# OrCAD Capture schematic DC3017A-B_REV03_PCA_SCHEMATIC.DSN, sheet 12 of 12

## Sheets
12 _10-PORTS 1-12 LEDS: size Custom
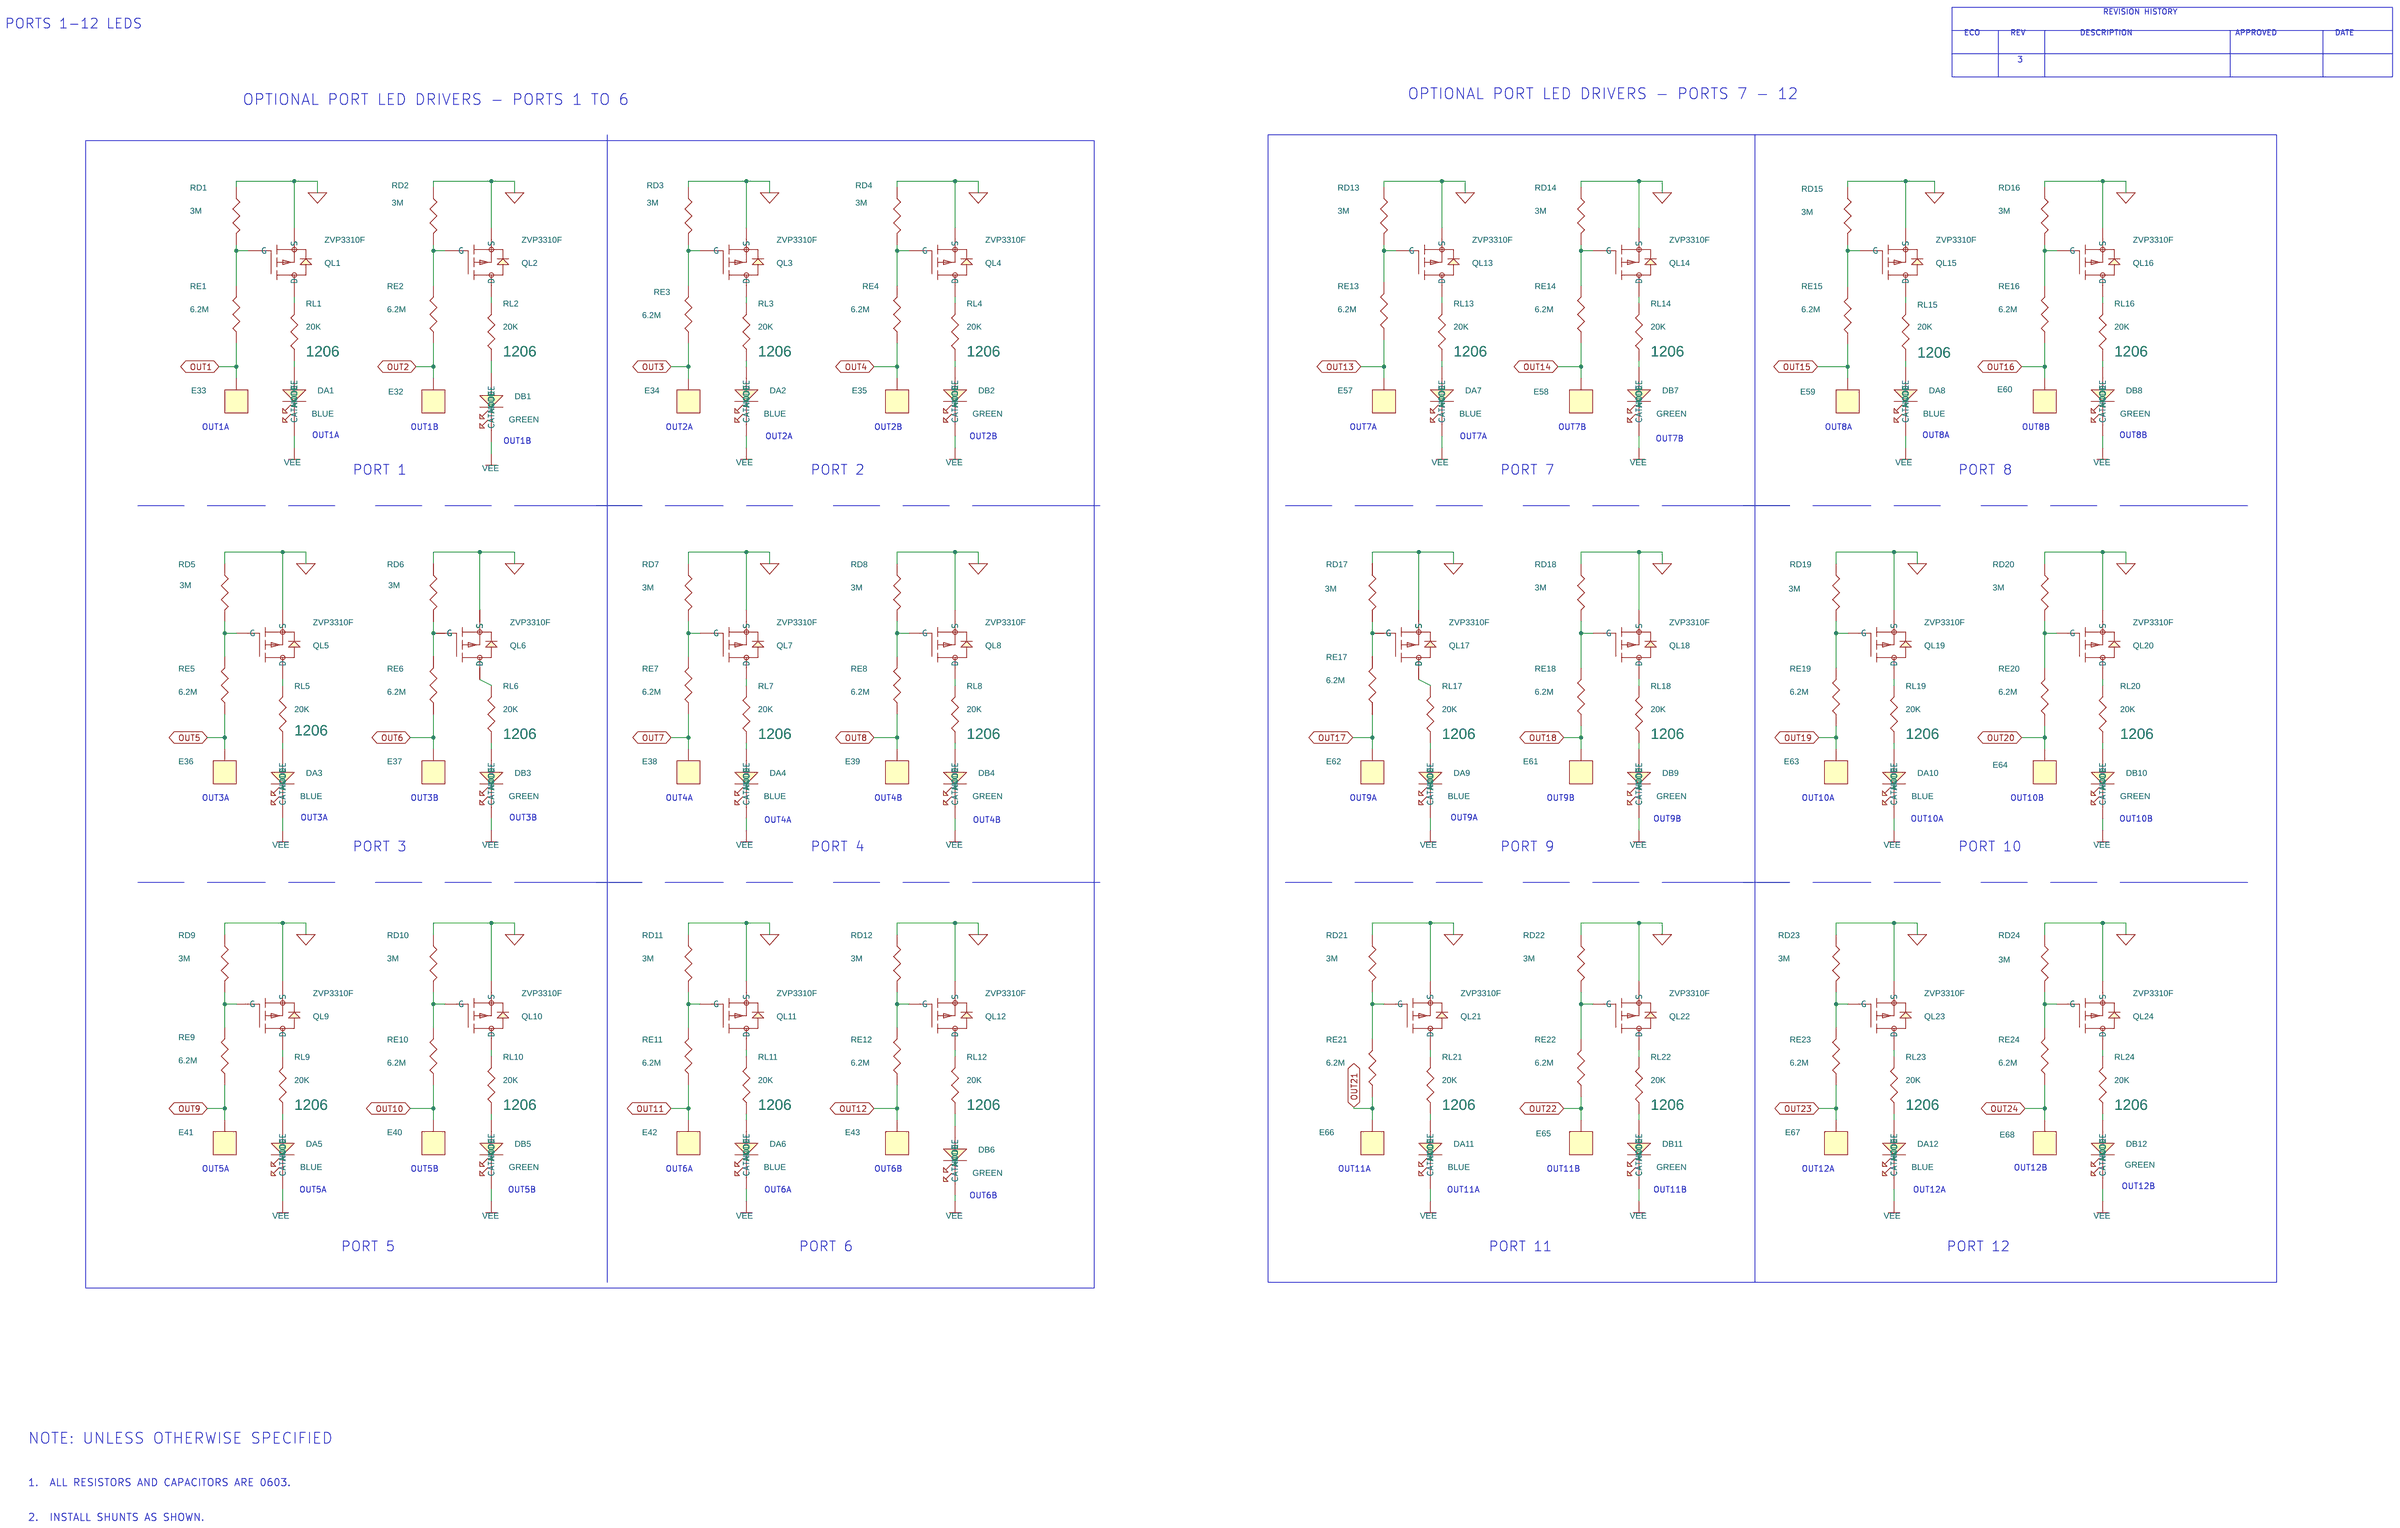
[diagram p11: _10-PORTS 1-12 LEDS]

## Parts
DA1  BLUE  [LED_0603]
DA2  BLUE  [LED_0603]
DA3  BLUE  [LED_0603]
DA4  BLUE  [LED_0603]
DA5  BLUE  [LED_0603]
DA6  BLUE  [LED_0603]
DA7  BLUE  [LED_0603]
DA8  BLUE  [LED_0603]
DA9  BLUE  [LED_0603]
DA10  BLUE  [LED_0603]
DA11  BLUE  [LED_0603]
DA12  BLUE  [LED_0603]
DB1  GREEN  [LED_0603]
DB2  GREEN  [LED_0603]
DB3  GREEN  [LED_0603]
DB4  GREEN  [LED_0603]
DB5  GREEN  [LED_0603]
DB6  GREEN  [LED_0603]
DB7  GREEN  [LED_0603]
DB8  GREEN  [LED_0603]
DB9  GREEN  [LED_0603]
DB10  GREEN  [LED_0603]
DB11  GREEN  [LED_0603]
DB12  GREEN  [LED_0603]
E32  TEST POINT  [KEYSTONE_5019]
E33  TEST POINT  [KEYSTONE_5019]
E34  TEST POINT  [KEYSTONE_5019]
E35  TEST POINT  [KEYSTONE_5019]
E36  TEST POINT  [KEYSTONE_5019]
E37  TEST POINT  [KEYSTONE_5019]
E38  TEST POINT  [KEYSTONE_5019]
E39  TEST POINT  [KEYSTONE_5019]
E40  TEST POINT  [KEYSTONE_5019]
E41  TEST POINT  [KEYSTONE_5019]
E42  TEST POINT  [KEYSTONE_5019]
E43  TEST POINT  [KEYSTONE_5019]
E57  TEST POINT  [KEYSTONE_5019]
E58  TEST POINT  [KEYSTONE_5019]
E59  TEST POINT  [KEYSTONE_5019]
E60  TEST POINT  [KEYSTONE_5019]
E61  TEST POINT  [KEYSTONE_5019]
E62  TEST POINT  [KEYSTONE_5019]
E63  TEST POINT  [KEYSTONE_5019]
E64  TEST POINT  [KEYSTONE_5019]
E65  TEST POINT  [KEYSTONE_5019]
E66  TEST POINT  [KEYSTONE_5019]
E67  TEST POINT  [KEYSTONE_5019]
E68  TEST POINT  [KEYSTONE_5019]
QL1  ZVP3310F  [SOT23-3N]
QL2  ZVP3310F  [SOT23-3N]
QL3  ZVP3310F  [SOT23-3N]
QL4  ZVP3310F  [SOT23-3N]
QL5  ZVP3310F  [SOT23-3N]
QL6  ZVP3310F  [SOT23-3N]
QL7  ZVP3310F  [SOT23-3N]
QL8  ZVP3310F  [SOT23-3N]
QL9  ZVP3310F  [SOT23-3N]
QL10  ZVP3310F  [SOT23-3N]
QL11  ZVP3310F  [SOT23-3N]
QL12  ZVP3310F  [SOT23-3N]
QL13  ZVP3310F  [SOT23-3N]
QL14  ZVP3310F  [SOT23-3N]
QL15  ZVP3310F  [SOT23-3N]
QL16  ZVP3310F  [SOT23-3N]
QL17  ZVP3310F  [SOT23-3N]
QL18  ZVP3310F  [SOT23-3N]
QL19  ZVP3310F  [SOT23-3N]
QL20  ZVP3310F  [SOT23-3N]
QL21  ZVP3310F  [SOT23-3N]
QL22  ZVP3310F  [SOT23-3N]
QL23  ZVP3310F  [SOT23-3N]
QL24  ZVP3310F  [SOT23-3N]
RD1  3M  [CR0603N]
RD2  3M  [CR0603N]
RD3  3M  [CR0603N]
RD4  3M  [CR0603N]
RD5  3M  [CR0603N]
RD6  3M  [CR0603N]
RD7  3M  [CR0603N]
RD8  3M  [CR0603N]
RD9  3M  [CR0603N]
RD10  3M  [CR0603N]
RD11  3M  [CR0603N]
RD12  3M  [CR0603N]
RD13  3M  [CR0603N]
RD14  3M  [CR0603N]
RD15  3M  [CR0603N]
RD16  3M  [CR0603N]
RD17  3M  [CR0603N]
RD18  3M  [CR0603N]
RD19  3M  [CR0603N]
RD20  3M  [CR0603N]
RD21  3M  [CR0603N]
RD22  3M  [CR0603N]
RD23  3M  [CR0603N]
RD24  3M  [CR0603N]
RE1  6.2M  [CR0603N]
RE2  6.2M  [CR0603N]
RE3  6.2M  [CR0603N]
RE4  6.2M  [CR0603N]
RE5  6.2M  [CR0603N]
RE6  6.2M  [CR0603N]
RE7  6.2M  [CR0603N]
RE8  6.2M  [CR0603N]
RE9  6.2M  [CR0603N]
RE10  6.2M  [CR0603N]
RE11  6.2M  [CR0603N]
RE12  6.2M  [CR0603N]
RE13  6.2M  [CR0603N]
RE14  6.2M  [CR0603N]
RE15  6.2M  [CR0603N]
RE16  6.2M  [CR0603N]
RE17  6.2M  [CR0603N]
RE18  6.2M  [CR0603N]
RE19  6.2M  [CR0603N]
RE20  6.2M  [CR0603N]
RE21  6.2M  [CR0603N]
RE22  6.2M  [CR0603N]
RE23  6.2M  [CR0603N]
RE24  6.2M  [CR0603N]
RL1  20K  [CR1206N]
RL2  20K  [CR1206N]
RL3  20K  [CR1206N]
RL4  20K  [CR1206N]
RL5  20K  [CR1206N]
RL6  20K  [CR1206N]
RL7  20K  [CR1206N]
RL8  20K  [CR1206N]
RL9  20K  [CR1206N]
RL10  20K  [CR1206N]
RL11  20K  [CR1206N]
RL12  20K  [CR1206N]
RL13  20K  [CR1206N]
RL14  20K  [CR1206N]
RL15  20K  [CR1206N]
RL16  20K  [CR1206N]
RL17  20K  [CR1206N]
RL18  20K  [CR1206N]
RL19  20K  [CR1206N]
RL20  20K  [CR1206N]
RL21  20K  [CR1206N]
RL22  20K  [CR1206N]
RL23  20K  [CR1206N]
RL24  20K  [CR1206N]

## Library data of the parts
DA1 = LED: LED,BLUE,WATER CLEAR,0603; 1ST PART FIELD: OUT1A; CLASS: DISCRETE; Inventory Qty: 0; Manufacturer: Wurth Elektronik; Manufacturer PN: 155060BS75300; PART_NUMBER: 270-0164; Package Type: 0603
DA2 = LED: LED,BLUE,WATER CLEAR,0603; 1ST PART FIELD: OUT3A; CLASS: DISCRETE; Inventory Qty: 0; Manufacturer: Wurth Elektronik; Manufacturer PN: 155060BS75300; PART_NUMBER: 270-0164; Package Type: 0603
DA3 = LED: LED,BLUE,WATER CLEAR,0603; 1ST PART FIELD: OUT2A; CLASS: DISCRETE; Inventory Qty: 0; Manufacturer: Wurth Elektronik; Manufacturer PN: 155060BS75300; PART_NUMBER: 270-0164; Package Type: 0603
DA4 = LED: LED,BLUE,WATER CLEAR,0603; 1ST PART FIELD: OUT4A; CLASS: DISCRETE; Inventory Qty: 0; Manufacturer: Wurth Elektronik; Manufacturer PN: 155060BS75300; PART_NUMBER: 270-0164; Package Type: 0603
DA5 = LED: LED,BLUE,WATER CLEAR,0603; 1ST PART FIELD: OUT5A; CLASS: DISCRETE; Inventory Qty: 0; Manufacturer: Wurth Elektronik; Manufacturer PN: 155060BS75300; PART_NUMBER: 270-0164; Package Type: 0603
DA6 = LED: LED,BLUE,WATER CLEAR,0603; 1ST PART FIELD: OUT6A; CLASS: DISCRETE; Inventory Qty: 0; Manufacturer: Wurth Elektronik; Manufacturer PN: 155060BS75300; PART_NUMBER: 270-0164; Package Type: 0603
DA7 = LED: LED,BLUE,WATER CLEAR,0603; 1ST PART FIELD: OUT7A; CLASS: DISCRETE; Inventory Qty: 0; Manufacturer: Wurth Elektronik; Manufacturer PN: 155060BS75300; PART_NUMBER: 270-0164; Package Type: 0603
DA8 = LED: LED,BLUE,WATER CLEAR,0603; 1ST PART FIELD: OUT8A; CLASS: DISCRETE; Inventory Qty: 0; Manufacturer: Wurth Elektronik; Manufacturer PN: 155060BS75300; PART_NUMBER: 270-0164; Package Type: 0603
DA9 = LED: LED,BLUE,WATER CLEAR,0603; 1ST PART FIELD: OUT9A; CLASS: DISCRETE; Inventory Qty: 0; Manufacturer: Wurth Elektronik; Manufacturer PN: 155060BS75300; PART_NUMBER: 270-0164; Package Type: 0603
DA10 = LED: LED,BLUE,WATER CLEAR,0603; 1ST PART FIELD: OUT10A; CLASS: DISCRETE; Inventory Qty: 0; Manufacturer: Wurth Elektronik; Manufacturer PN: 155060BS75300; PART_NUMBER: 270-0164; Package Type: 0603
DA11 = LED: LED,BLUE,WATER CLEAR,0603; 1ST PART FIELD: OUT11A; CLASS: DISCRETE; Inventory Qty: 0; Manufacturer: Wurth Elektronik; Manufacturer PN: 155060BS75300; PART_NUMBER: 270-0164; Package Type: 0603
DA12 = LED: LED,BLUE,WATER CLEAR,0603; 1ST PART FIELD: OUT12A; CLASS: DISCRETE; Inventory Qty: 0; Manufacturer: Wurth Elektronik; Manufacturer PN: 155060BS75300; PART_NUMBER: 270-0164; Package Type: 0603
DB1 = LED: LED,GREEN,DIFFUSED,0603; 1ST PART FIELD: OUT1B; CLASS: DISCRETE; Inventory Qty: 4424; Manufacturer: ROHM; Manufacturer PN: SML-E12P8WT86; PART_NUMBER: 270-0176; Package Type: 0603
DB2 = LED: LED,GREEN,DIFFUSED,0603; 1ST PART FIELD: OUT3B; CLASS: DISCRETE; Inventory Qty: 4424; Manufacturer: ROHM; Manufacturer PN: SML-E12P8WT86; PART_NUMBER: 270-0176; Package Type: 0603
DB3 = LED: LED,GREEN,DIFFUSED,0603; 1ST PART FIELD: OUT2B; CLASS: DISCRETE; Inventory Qty: 4424; Manufacturer: ROHM; Manufacturer PN: SML-E12P8WT86; PART_NUMBER: 270-0176; Package Type: 0603
DB4 = LED: LED,GREEN,DIFFUSED,0603; 1ST PART FIELD: OUT4B; CLASS: DISCRETE; Inventory Qty: 4424; Manufacturer: ROHM; Manufacturer PN: SML-E12P8WT86; PART_NUMBER: 270-0176; Package Type: 0603
DB5 = LED: LED,GREEN,DIFFUSED,0603; 1ST PART FIELD: OUT5B; CLASS: DISCRETE; Inventory Qty: 4424; Manufacturer: ROHM; Manufacturer PN: SML-E12P8WT86; PART_NUMBER: 270-0176; Package Type: 0603
DB6 = LED: LED,GREEN,DIFFUSED,0603; 1ST PART FIELD: OUT6B; CLASS: DISCRETE; Inventory Qty: 4424; Manufacturer: ROHM; Manufacturer PN: SML-E12P8WT86; PART_NUMBER: 270-0176; Package Type: 0603
DB7 = LED: LED,GREEN,DIFFUSED,0603; 1ST PART FIELD: OUT7B; CLASS: DISCRETE; Inventory Qty: 4424; Manufacturer: ROHM; Manufacturer PN: SML-E12P8WT86; PART_NUMBER: 270-0176; Package Type: 0603
DB8 = LED: LED,GREEN,DIFFUSED,0603; 1ST PART FIELD: OUT8B; CLASS: DISCRETE; Inventory Qty: 4424; Manufacturer: ROHM; Manufacturer PN: SML-E12P8WT86; PART_NUMBER: 270-0176; Package Type: 0603
DB9 = LED: LED,GREEN,DIFFUSED,0603; 1ST PART FIELD: OUT9B; CLASS: DISCRETE; Inventory Qty: 4424; Manufacturer: ROHM; Manufacturer PN: SML-E12P8WT86; PART_NUMBER: 270-0176; Package Type: 0603
DB10 = LED: LED,GREEN,DIFFUSED,0603; 1ST PART FIELD: OUT10B; CLASS: DISCRETE; Inventory Qty: 4424; Manufacturer: ROHM; Manufacturer PN: SML-E12P8WT86; PART_NUMBER: 270-0176; Package Type: 0603
DB11 = LED: LED,GREEN,DIFFUSED,0603; 1ST PART FIELD: OUT11B; CLASS: DISCRETE; Inventory Qty: 4424; Manufacturer: ROHM; Manufacturer PN: SML-E12P8WT86; PART_NUMBER: 270-0176; Package Type: 0603
DB12 = LED: LED,GREEN,DIFFUSED,0603; 1ST PART FIELD: OUT12B; CLASS: DISCRETE; Inventory Qty: 4424; Manufacturer: ROHM; Manufacturer PN: SML-E12P8WT86; PART_NUMBER: 270-0176; Package Type: 0603
E32-E35 E39 E57-E60 = MP-PINNED: TEST POINT,SILVER PLATE,PHOSPHOR BRONZE,3.81x2.03mm,2.29mm H,SMT; CLASS: DISCRETE; COMPFIXED: POS; Inventory Qty: 40128; Manufacturer: KEYSTONE; Manufacturer PN: 5019; PART_NUMBER: 260-0018; Package Size: 0.15" L x 0.080" W; Part Number: KEYSTONE-5019
E36-E38 E40-E43 E61-E68 = MP-PINNED: TEST POINT,SILVER PLATE,PHOSPHOR BRONZE,3.81x2.03mm,2.29mm H,SMT; CLASS: DISCRETE; Inventory Qty: 40128; Manufacturer: KEYSTONE; Manufacturer PN: 5019; PART_NUMBER: 260-0018; Package Size: 0.15" L x 0.080" W
QL1-QL24 = 3P_P-CH_TYPE1A: XSTR.,MOSFET,P-CH,100V,75mA,SOT-23-3; CLASS: DISCRETE; FPLIST: SOT23-3N,SOT23-3L,SOT23-3M; Inventory Qty: 10248; Manufacturer: DIODES INC.; Manufacturer PN: ZVP3310FTA; PART_NUMBER: 240-0366; Package Type: SOT-23-3; Rated Voltage: 100V
RD1-RD24 = RES: RES.,3M OHMS,1%,1/10W,0603; 1ST PART FIELD: 1%; CLASS: DISCRETE; FPLIST: CR0603N,CR0603L,CR0603M; Inventory Qty: 20000; Manufacturer: VISHAY; Manufacturer PN: CRCW06033M00FKEA; PART_NUMBER: 100-0479; Package Size: 0603; Part Number: ACC  CR16-914JM; Rated Power: 1/10W; Temperature Coefficient: 100ppm; Tolerance: 1%
RE1-RE24 = RES: RES.,6.2M OHMS,1%,1/10W,0603,AEC-Q200; CLASS: DISCRETE; FPLIST: CR0603N,CR0603L,CR0603M; Inventory Qty: 0; Manufacturer: VISHAY; Manufacturer PN: CRCW06036M20FKEA; PART_NUMBER: 100-1862; Package Size: 0603; Rated Power: 1/10W; Temperature Coefficient: +/-100ppm; Tolerance: 1%
RL1-RL24 = RES: RES.,20k OHMS,1%,1/4W,1206,AEC-Q200; 4TH PART FIELD: VISHAY,; CLASS: DISCRETE; FPLIST: CR1206N,CR1206L,CR1206M; Inventory Qty: 28804; Manufacturer: PANASONIC; Manufacturer PN: ERJ8ENF2002V; PART_NUMBER: 100-0607; Package Size: 1206; Rated Power: 1/4W; Temperature Coefficient: 100PPM; Tolerance: 1%

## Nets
Agnd: QL1.2(S) QL2.2(S) QL3.2(S) QL4.2(S) QL5.2(S) QL6.2(S) QL7.2(S) QL8.2(S) QL9.2(S) QL10.2(S) QL11.2(S) QL12.2(S) QL13.2(S) QL14.2(S) QL15.2(S) QL16.2(S) QL17.2(S) QL18.2(S) QL19.2(S) QL20.2(S) QL21.2(S) QL22.2(S) QL23.2(S) QL24.2(S) RD1.1 RD2.1 RD3.1 RD4.1 RD5.1 RD6.1 RD7.1 RD8.1 RD9.1 RD10.1 RD11.1 RD12.1 RD13.1 RD14.1 RD15.1 RD16.1 RD17.1 RD18.1 RD19.1 RD20.1 RD21.1 RD22.1 RD23.1 RD24.1 ; also on sheet 1 2 3 4 5 6 7 8 9 11
VEE: DA1.1(CATHODE) DA2.1(CATHODE) DA3.1(CATHODE) DA4.1(CATHODE) DA5.1(CATHODE) DA6.1(CATHODE) DA7.1(CATHODE) DA8.1(CATHODE) DA9.1(CATHODE) DA10.1(CATHODE) DA11.1(CATHODE) DA12.1(CATHODE) DB1.1(CATHODE) DB2.1(CATHODE) DB3.1(CATHODE) DB4.1(CATHODE) DB5.1(CATHODE) DB6.1(CATHODE) DB7.1(CATHODE) DB8.1(CATHODE) DB9.1(CATHODE) DB10.1(CATHODE) DB11.1(CATHODE) DB12.1(CATHODE) ; also on sheet 1 2 3 4 11
OUT1: E33.1 RE1.1 ; also on sheet 3 4
OUT2: E32.1 RE2.1 ; also on sheet 3 4
OUT3: E34.1 RE3.1 ; also on sheet 3 4
OUT4: E35.1 RE4.1 ; also on sheet 3 4
OUT5: E36.1 RE5.1 ; also on sheet 3 4
OUT6: E37.1 RE6.1 ; also on sheet 3 4
OUT7: E38.1 RE7.1 ; also on sheet 3 4
OUT8: E39.1 RE8.1 ; also on sheet 3 4
OUT9: E41.1 RE9.1 ; also on sheet 3 5
OUT10: E40.1 RE10.1 ; also on sheet 3 5
OUT11: E42.1 RE11.1 ; also on sheet 3 5
OUT12: E43.1 RE12.1 ; also on sheet 3 5
OUT13: E57.1 RE13.1 ; also on sheet 3 5
OUT14: E58.1 RE14.1 ; also on sheet 3 5
OUT15: E59.1 RE15.1 ; also on sheet 3 5
OUT16: E60.1 RE16.1 ; also on sheet 3 5
OUT17: E62.1 RE17.1 ; also on sheet 3 6
OUT18: E61.1 RE18.1 ; also on sheet 3 6
OUT19: E63.1 RE19.1 ; also on sheet 3 6
OUT20: E64.1 RE20.1 ; also on sheet 3 6
OUT21: E66.1 RE21.1 ; also on sheet 3 6
OUT22: E65.1 RE22.1 ; also on sheet 3 6
OUT23: E67.1 RE23.1 ; also on sheet 3 6
OUT24: E68.1 RE24.1 ; also on sheet 3 6
N22006829: QL1.1(G) RD1.2 RE1.2
N22006845: QL2.1(G) RD2.2 RE2.2
N22009148: QL3.1(G) RD3.2 RE3.2
N22009164: QL4.1(G) RD4.2 RE4.2
N22011509: QL5.1(G) RD5.2 RE5.2
N22011525: QL6.1(G) RD6.2 RE6.2
N22011719: QL7.1(G) RD7.2 RE7.2
N22011745: QL8.1(G) RD8.2 RE8.2
N22012654: DA6.2(ANODE) RL11.1
N22012658: QL11.1(G) RD11.2 RE11.2
N22012674: QL12.1(G) RD12.2 RE12.2
N22049431: QL13.1(G) RD13.2 RE13.2
N22049634: DA8.2(ANODE) RL15.1
N22049638: QL15.1(G) RD15.2 RE15.2
N22049651: QL16.1(G) RD16.2 RE16.2
N22049842: QL17.1(G) RD17.2 RE17.2
N22049858: QL18.1(G) RD18.2 RE18.2
N22050048: QL19.1(G) RD19.2 RE19.2
N22050232: QL21.1(G) RD21.2 RE21.2
N22050252: QL22.1(G) RD22.2 RE22.2
N22050421: QL23.1(G) RD23.2 RE23.2
N22673373: QL24.1(G) RD24.2 RE24.2
N22673751: QL9.1(G) RD9.2 RE9.2
N22673815: QL10.1(G) RD10.2 RE10.2
N22673899: QL14.1(G) RD14.2 RE14.2
N23120182: QL20.1(G) RD20.2 RE20.2
N23297331: QL1.3(D) RL1.2
N23297336: DA1.2(ANODE) RL1.1
N23297632: QL2.3(D) RL2.2
N23297871: DB1.2(ANODE) RL2.1
N23317927: DB5.2(ANODE) RL10.1
N23345007: DA2.2(ANODE) RL3.1
N23345051: QL3.3(D) RL3.2
N23345200: QL4.3(D) RL4.2
N23345240: DB2.2(ANODE) RL4.1
N23345448: QL5.3(D) RL5.2
N23345487: DA3.2(ANODE) RL5.1
N23345493: QL6.3(D) RL6.2
N23345532: DB3.2(ANODE) RL6.1
N23345538: QL7.3(D) RL7.2
N23345578: DA4.2(ANODE) RL7.1
N23345584: QL8.3(D) RL8.2
N23345623: DB4.2(ANODE) RL8.1
N23345669: QL9.3(D) RL9.2
N23345675: DA5.2(ANODE) RL9.1
N23345721: QL10.3(D) RL10.2
N23345767: QL11.3(D) RL11.2
N23345773: QL12.3(D) RL12.2
N23345937: DB6.2(ANODE) RL12.1
N23346650: QL15.3(D) RL15.2
N23347155: QL13.3(D) RL13.2
N23347182: QL14.3(D) RL14.2
N23347236: QL16.3(D) RL16.2
N23347361: DA7.2(ANODE) RL13.1
N23347367: DB7.2(ANODE) RL14.1
N23347384: DB8.2(ANODE) RL16.1
N23347390: QL17.3(D) RL17.2
N23347452: QL18.3(D) RL18.2
N23347483: QL19.3(D) RL19.2
N23347514: QL20.3(D) RL20.2
N23347545: DB10.2(ANODE) RL20.1
N23347551: DA10.2(ANODE) RL19.1
N23347557: DB9.2(ANODE) RL18.1
N23347563: DA9.2(ANODE) RL17.1
N23347737: QL21.3(D) RL21.2
N23347768: DA11.2(ANODE) RL21.1
N23347774: QL22.3(D) RL22.2
N23347805: DB11.2(ANODE) RL22.1
N23347811: QL23.3(D) RL23.2
N23347842: DA12.2(ANODE) RL23.1
N23347848: QL24.3(D) RL24.2
N23347879: DB12.2(ANODE) RL24.1

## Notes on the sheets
sheet 12
- REVISION HISTORY
- PORTS 1-12 LEDS
- ECO
- REV
- DESCRIPTION
- APPROVED
- DATE
- 3
- OPTIONAL PORT LED DRIVERS - PORTS 1 TO 6
- OPTIONAL PORT LED DRIVERS - PORTS 7 - 12
- OUT1A
- OUT1A
- OUT1B
- OUT2A
- OUT2A
- OUT2B
- OUT2B
- OUT7A
- OUT7A
- OUT7B
- OUT7B
- OUT8A
- OUT8A
- OUT8B
- OUT8B
- OUT1B
- PORT 1
- PORT 2
- PORT 7
- PORT 8
- OUT3A
- OUT3B
- OUT4A
- OUT4B
- OUT9A
- OUT9B
- OUT10A
- OUT10B
- OUT3A
- OUT3B
- OUT4A
- OUT4B
- OUT9A
- OUT9B
- OUT10A
- OUT10B
- PORT 3
- PORT 4
- PORT 9
- PORT 10
- OUT5A
- OUT5B
- OUT6A
- OUT6B
- OUT11A
- OUT11B
- OUT12A
- OUT12B
- OUT5A
- OUT5B
- OUT6A
- OUT11A
- OUT11B
- OUT12A
- OUT12B
- OUT6B
- PORT 5
- PORT 6
- PORT 11
- PORT 12
- NOTE: UNLESS OTHERWISE SPECIFIED
- 1.  ALL RESISTORS AND CAPACITORS ARE 0603.
- 2.  INSTALL SHUNTS AS SHOWN.
